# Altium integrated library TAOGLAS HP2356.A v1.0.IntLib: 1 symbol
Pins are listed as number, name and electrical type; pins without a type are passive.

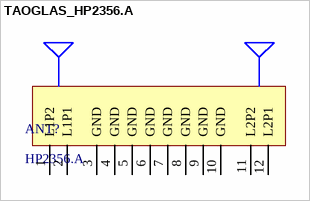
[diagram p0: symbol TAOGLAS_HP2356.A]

## TAOGLAS_HP2356.A
designator ANT?, comment HP2356.A
High precision GNSS L1/L2 Patch 35*35*6mm; ComponentLibStatus: Created; MFG: Taoglas; Temp_High: +85C; Temp_Low: -40C
footprint TAOGLAS_HP2356.A (High precision GNSS L1/L2 Patch 35*35*6mm)
pins: 1 L1P2, 2 L1P1, 3 GND, 4 GND, 5 GND, 6 GND, 7 GND, 8 GND, 9 GND, 10 GND, 11 L2P2, 12 L2P1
